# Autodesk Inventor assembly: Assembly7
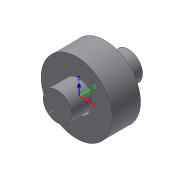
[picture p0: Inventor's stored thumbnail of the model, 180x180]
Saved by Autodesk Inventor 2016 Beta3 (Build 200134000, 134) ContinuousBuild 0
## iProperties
Created: 2016-03
Part Number: Assembly7
Document SubType Name: Assembly
Designer: Gaurav
Author: Gaurav
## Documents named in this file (3)
- D:\My Data\Books_Final Books\Autodesk Inventor 2015_resources\Chapter 7\Constraint_set\Assembly7.iam
- D:\My Data\Books_Final Books\Autodesk Inventor 2015_resources\Chapter 7\Constraint_set\Base.ipt
- D:\My Data\Books_Final Books\Autodesk Inventor 2015_resources\Chapter 7\Constraint_set\insert.ipt
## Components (2 placed, 2 different names)
1. Base:1 — Mate:1, Mate:2
2. insert:1 — Flush:3
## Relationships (3: Mate 2, Flush 1)
- Mate:1: Base:1
- Mate:2: Base:1
- Flush:3: insert:1
